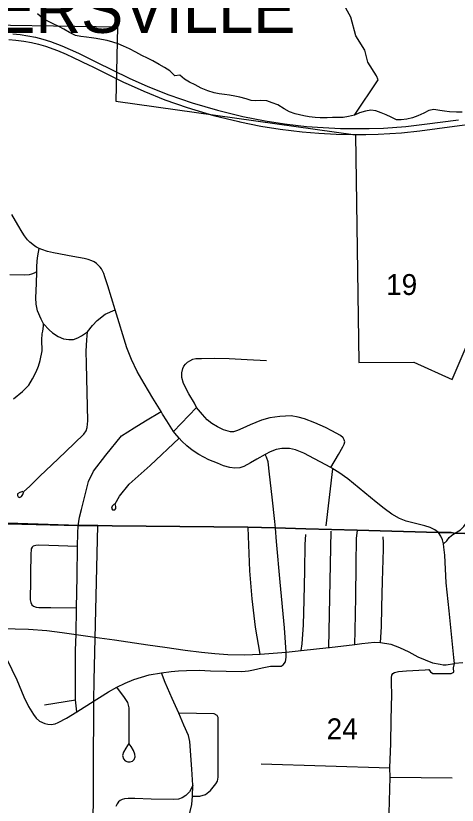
# Model space of a CAD drawing. Extents: x 0 to 34, y 0 to 22.
# Drawn here: x 6.345 to 7.23, y 15.187 to 16.768 of the extents above; entities that cross this region are included whole.
import ezdxf

# ---------------------------------------------------------------- set-up
doc = ezdxf.new("R2010")
doc.units = 0
for name, color, linetype in [('GM_X_City_Street', 7, 'Continuous'), ('GM_X_Corporation', 7, 'Continuous'), ('GM_X_Corporation_Text', 7, 'Continuous'), ('GM_X_County_Road', 7, 'Continuous'), ('GM_X_Minor_River', 7, 'Continuous'), ('GM_X_Section_Text', 7, 'Continuous'), ('GM_X_State_Route', 7, 'Continuous'), ('GM_X_Township_Road', 7, 'Continuous'), ('GM_X_US_Route', 7, 'Continuous')]:
    doc.layers.add(name, color=color, linetype=linetype)

msp = doc.modelspace()

# ---------------------------------------------------------------- linework, layer by layer
at = {"layer": 'GM_X_City_Street'}
for p, q in [((6.6615, 15.9355), (6.7076, 15.9837)), ((6.9669, 15.7469), (6.9804, 15.8611)), ((6.9725, 15.5033), (6.9773, 15.736)), ((6.8369, 15.2705), (7.0949, 15.2625)), ((7.0951, 15.2437), (7.2198, 15.2421))]:
    msp.add_line(p, q, dxfattribs=at)
for points in [[(6.3412, 16.0009), (6.359, 16.0156), (6.3716, 16.0286), (6.379, 16.041), (6.3865, 16.0549), (6.3909, 16.0667), (6.3942, 16.0776), (6.3981, 16.097), (6.3977, 16.1195), (6.3982, 16.1312), (6.3996, 16.1368), (6.4008, 16.1467), (6.4009, 16.1516), (6.3963, 16.1606), (6.389, 16.1776), (6.3862, 16.1905), (6.3855, 16.2032), (6.3867, 16.2322), (6.3875, 16.2555), (6.3879, 16.2647), (6.3886, 16.2776), (6.3894, 16.2877), (6.3924, 16.3018)], [(6.3867, 16.2554), (6.3826, 16.253), (6.3769, 16.2508), (6.3723, 16.2496), (6.3629, 16.2484), (6.3334, 16.2491)], [(6.3594, 15.8154), (6.3537, 15.8133), (6.3492, 15.8108), (6.3487, 15.8074), (6.3504, 15.8046), (6.3532, 15.8035), (6.357, 15.8056), (6.3593, 15.8095), (6.3614, 15.8154), (6.3731, 15.8257), (6.3936, 15.8461), (6.4176, 15.8691), (6.4448, 15.8951), (6.4821, 15.9306), (6.4863, 15.9369), (6.4887, 15.9436), (6.4899, 15.9573), (6.4872, 16.0709), (6.4867, 16.0967), (6.4875, 16.1195), (6.4891, 16.135), (6.4994, 16.1481), (6.5085, 16.1578), (6.5245, 16.1709), (6.5442, 16.1793)], [(6.4009, 16.1516), (6.4125, 16.1393), (6.4188, 16.1334), (6.4301, 16.1261), (6.4412, 16.1214), (6.4515, 16.1196), (6.4612, 16.1202), (6.4697, 16.123), (6.4774, 16.1271), (6.4891, 16.135)], [(6.9767, 15.8634), (6.9916, 15.8896), (7.0005, 15.9049), (7.0032, 15.9106), (7.0043, 15.9151), (7.0035, 15.9189), (7.001, 15.923), (6.9959, 15.9276), (6.9873, 15.9325), (6.9788, 15.9367), (6.9656, 15.9439), (6.9441, 15.953), (6.9234, 15.9611), (6.9109, 15.9647), (6.8969, 15.967), (6.8743, 15.9658), (6.8541, 15.963), (6.8373, 15.9587), (6.8148, 15.9492), (6.7999, 15.9426), (6.7895, 15.9376), (6.7816, 15.9351), (6.7755, 15.9349), (6.7616, 15.9388), (6.7492, 15.9448), (6.7381, 15.9517), (6.7291, 15.9589), (6.7194, 15.9698), (6.7076, 15.9837), (6.7034, 15.9926), (6.6923, 16.0108), (6.6817, 16.0315), (6.6783, 16.0438), (6.6782, 16.0531), (6.6799, 16.0615), (6.6819, 16.0662), (6.6852, 16.0704), (6.6895, 16.0742), (6.6941, 16.0774), (6.7004, 16.0804), (6.706, 16.0817), (6.7177, 16.0821), (6.7436, 16.0826), (6.773, 16.0816), (6.8091, 16.08), (6.8479, 16.0781)], [(6.4704, 15.7468), (6.4733, 15.7644), (6.477, 15.7798), (6.4842, 15.809), (6.4909, 15.8358), (6.5009, 15.8561), (6.5258, 15.8885), (6.5572, 15.927), (6.5824, 15.9433), (6.6054, 15.9573), (6.6364, 15.9757)], [(6.5433, 15.7905), (6.5413, 15.789), (6.5382, 15.7863), (6.5371, 15.7823), (6.539, 15.7786), (6.5438, 15.7786), (6.5459, 15.7815), (6.546, 15.7853), (6.5449, 15.7881), (6.5446, 15.7911), (6.553, 15.8065), (6.5725, 15.8301), (6.6144, 15.8677), (6.6727, 15.9221)], [(6.8868, 15.4941), (6.8838, 15.5423), (6.8748, 15.6341), (6.8679, 15.7153), (6.8655, 15.7422), (6.8643, 15.7556), (6.8589, 15.8043), (6.8538, 15.8505), (6.851, 15.8749), (6.8479, 15.8846), (6.8448, 15.8899)], [(6.8348, 15.4895), (6.8257, 15.544), (6.8192, 15.6004), (6.8142, 15.6565), (6.8107, 15.7437)], [(6.9173, 15.4972), (6.9189, 15.5107), (6.9217, 15.5484), (6.9231, 15.5979), (6.9243, 15.6575), (6.925, 15.7093), (6.9265, 15.7293)], [(7.0243, 15.5092), (7.025, 15.5369), (7.0263, 15.6037), (7.0275, 15.6687), (7.0282, 15.722), (7.0296, 15.7377), (7.0298, 15.739)], [(7.0761, 15.5133), (7.0781, 15.5442), (7.0789, 15.5839), (7.0802, 15.6357), (7.0818, 15.6998), (7.0822, 15.7131), (7.0811, 15.7246)], [(7.0936, 15.1715), (7.0951, 15.2437), (7.0949, 15.2625), (7.0969, 15.311), (7.0975, 15.3585), (7.0985, 15.4099), (7.0978, 15.4311), (7.0979, 15.439), (7.0981, 15.4434), (7.0987, 15.4476), (7.1006, 15.4509), (7.1039, 15.4533), (7.1121, 15.455), (7.1283, 15.4562), (7.1654, 15.4581), (7.1726, 15.4591), (7.1764, 15.4545), (7.1807, 15.4514), (7.2175, 15.4513), (7.2226, 15.4535), (7.2224, 15.4627), (7.2243, 15.4708)], [(6.7001, 15.2275), (6.6978, 15.2596), (6.6943, 15.3147), (6.6911, 15.3269), (6.6822, 15.3475), (6.672, 15.3718), (6.6587, 15.4013), (6.6449, 15.4332), (6.6374, 15.4526)], [(6.5721, 15.3107), (6.5692, 15.3072), (6.5658, 15.3013), (6.5611, 15.2934), (6.5593, 15.2869), (6.561, 15.2802), (6.5647, 15.2761), (6.5701, 15.274), (6.5743, 15.2741), (6.579, 15.2755), (6.5828, 15.2789), (6.5849, 15.2844), (6.584, 15.2898), (6.5813, 15.2968), (6.5767, 15.3048), (6.5728, 15.3105), (6.5724, 15.3273), (6.5728, 15.3624), (6.5727, 15.3826), (6.5699, 15.3928), (6.5635, 15.403), (6.5482, 15.4237)], [(6.6997, 15.2055), (6.7138, 15.2053), (6.7253, 15.2086), (6.7356, 15.2168), (6.746, 15.2302), (6.7493, 15.2354), (6.7506, 15.2436), (6.7508, 15.2882), (6.7511, 15.3627), (6.7486, 15.3673), (6.7429, 15.37), (6.672, 15.3718)], [(6.7001, 15.2275), (6.6967, 15.22), (6.6931, 15.214), (6.686, 15.207), (6.679, 15.2023), (6.6713, 15.1994), (6.6614, 15.1987), (6.6169, 15.1997), (6.5841, 15.2006), (6.5704, 15.2009), (6.5633, 15.2004), (6.5585, 15.1987), (6.5546, 15.1968), (6.5515, 15.194), (6.5485, 15.19), (6.546, 15.1845)], [(6.6911, 15.1605), (6.6979, 15.1888), (6.6997, 15.2055), (6.7001, 15.2275)]]:
    msp.add_lwpolyline(points, dxfattribs=at)
at = {"layer": 'GM_X_Corporation'}
for points in [[(5.8633, 16.7565), (6.5495, 16.7462), (6.5461, 16.597), (7.0261, 16.5297), (7.0326, 16.0736), (7.143, 16.0746), (7.2194, 16.0401), (7.3126, 16.2562)], [(5.4664, 15.7674), (5.6014, 15.7658), (5.6068, 15.7657), (5.6123, 15.7657), (5.7944, 15.7634), (6.4702, 15.7474), (6.8105, 15.7443), (6.8653, 15.7428), (6.9267, 15.7411), (7.0294, 15.7382), (7.1916, 15.7337), (7.2174, 15.7331), (7.2238, 15.7321), (7.3532, 15.7283), (7.8346, 15.7173), (8.2379, 15.708), (8.2436, 15.7079), (8.2556, 15.7096), (8.4088, 15.7047), (8.4164, 15.7046), (8.9, 15.6953), (8.9, 16.3396)], [(4.5503, 14.1), (8.9, 14.1), (8.9, 15.6953), (8.4164, 15.7046), (8.4088, 15.7047), (8.2556, 15.7096), (8.2436, 15.7079), (8.2379, 15.708), (7.8346, 15.7173), (7.3532, 15.7283), (7.2238, 15.7321), (7.2174, 15.7331), (7.1916, 15.7337), (7.0294, 15.7382), (6.9267, 15.7411), (6.8653, 15.7428), (6.8105, 15.7443), (6.4702, 15.7474), (5.7944, 15.7634), (5.6123, 15.7657), (5.6068, 15.7657), (5.6014, 15.7658), (5.4664, 15.7674)], [(6.5, 14.9635), (6.502, 15.3971), (6.5022, 15.4372), (6.5096, 15.7475), (6.4714, 15.7474), (6.2879, 15.7537)]]:
    msp.add_lwpolyline(points, dxfattribs=at)
at = {"layer": 'GM_X_County_Road'}
for points in [[(6.2927, 15.5405), (6.3175, 15.541), (6.371, 15.5398), (6.4077, 15.5372), (6.4382, 15.5331), (6.4667, 15.529)], [(6.2927, 15.5405), (6.2978, 15.5242), (6.3003, 15.5205), (6.3061, 15.514), (6.3122, 15.5073), (6.3174, 15.5004), (6.3474, 15.4383), (6.3618, 15.4045), (6.3711, 15.3851), (6.3807, 15.3689), (6.3866, 15.3614), (6.3929, 15.3557), (6.4036, 15.3508), (6.4096, 15.3495), (6.4166, 15.3492), (6.4241, 15.35), (6.4307, 15.3528), (6.4469, 15.3618), (6.4675, 15.3746), (6.5022, 15.3966), (6.5132, 15.4033)], [(6.4667, 15.529), (6.5131, 15.5224), (6.5429, 15.5182)], [(6.5429, 15.5182), (6.6101, 15.5088), (6.6438, 15.5038), (6.6846, 15.4977), (6.7174, 15.4937), (6.744, 15.4909), (6.7705, 15.4892), (6.8041, 15.4887), (6.8348, 15.4895), (6.8868, 15.4941), (6.9173, 15.4972), (6.9725, 15.5033), (6.9735, 15.5034)], [(6.9735, 15.5034), (7.0243, 15.5092), (7.0384, 15.5113), (7.0642, 15.5137), (7.0761, 15.5133), (7.0966, 15.5096), (7.1137, 15.5034), (7.1326, 15.4946), (7.151, 15.4846), (7.1801, 15.4726), (7.1953, 15.4695), (7.2016, 15.4687), (7.2074, 15.4686), (7.2243, 15.4708)], [(6.8594, 15.4658), (6.8705, 15.466), (6.8769, 15.4658), (6.8809, 15.4687), (6.8856, 15.4747), (6.887, 15.4837), (6.8868, 15.4941)], [(6.5132, 15.4033), (6.531, 15.4142), (6.5482, 15.4237), (6.5644, 15.4318), (6.5822, 15.439), (6.6127, 15.4485), (6.6374, 15.4526), (6.6569, 15.4553), (6.6712, 15.4566), (6.6876, 15.4573), (6.713, 15.4575), (6.7354, 15.4566), (6.7983, 15.4554), (6.8116, 15.4565), (6.8215, 15.4584), (6.8387, 15.4625), (6.8554, 15.4658), (6.8594, 15.4658)]]:
    msp.add_lwpolyline(points, dxfattribs=at)
at = {"layer": 'GM_X_Minor_River'}
for points in [[(7.0236, 16.5692), (7.0711, 16.6397), (7.0676, 16.6477), (7.0504, 16.6751), (7.0443, 16.6993), (7.0264, 16.7279), (7.0163, 16.7654), (6.9905, 16.8128)], [(7.0236, 16.5692), (7.0119, 16.5662), (7.0009, 16.5647), (6.9903, 16.5647), (6.9796, 16.5644), (6.969, 16.5637), (6.955, 16.5636), (6.945, 16.5645), (6.9328, 16.566), (6.9221, 16.5679), (6.9053, 16.5719), (6.8937, 16.5758), (6.8829, 16.5819), (6.8705, 16.5899), (6.8593, 16.5941), (6.8482, 16.5975), (6.836, 16.5983), (6.8265, 16.598), (6.8166, 16.5984), (6.8066, 16.6019), (6.794, 16.6053), (6.784, 16.6073), (6.7733, 16.6092), (6.7638, 16.6108), (6.7527, 16.6116), (6.7427, 16.614), (6.7301, 16.6178), (6.7166, 16.6234), (6.705, 16.6299), (6.6934, 16.6352), (6.6837, 16.6414), (6.674, 16.6495), (6.6641, 16.648), (6.6543, 16.6576), (6.6431, 16.6648), (6.6326, 16.6706), (6.6202, 16.6778), (6.609, 16.6832), (6.5982, 16.6889), (6.5862, 16.6954), (6.5731, 16.7018), (6.5615, 16.7075), (6.5507, 16.7121), (6.5396, 16.7156), (6.5284, 16.7186), (6.517, 16.7206), (6.5067, 16.7225), (6.4971, 16.7237), (6.4868, 16.7253), (6.4757, 16.7269), (6.4654, 16.7288), (6.4531, 16.7345), (6.4414, 16.741), (6.4314, 16.7464), (6.4206, 16.7521), (6.4098, 16.7571), (6.3993, 16.7636), (6.3891, 16.7721)], [(7.2397, 16.5752), (7.2283, 16.5752), (7.2139, 16.5759), (7.2043, 16.5768), (7.1948, 16.5787), (7.1825, 16.5806), (7.1727, 16.5784), (7.1626, 16.5732), (7.1506, 16.5675), (7.1397, 16.5637), (7.1288, 16.5611), (7.1174, 16.5596), (7.1079, 16.5601), (7.0971, 16.565), (7.0874, 16.5697), (7.0771, 16.5735), (7.0667, 16.5778), (7.0567, 16.579), (7.0458, 16.5771), (7.0341, 16.5737), (7.0236, 16.5692)]]:
    msp.add_lwpolyline(points, dxfattribs=at)
at = {"layer": 'GM_X_State_Route'}
for points in [[(7.2243, 15.4708), (7.223, 15.4834), (7.2132, 15.5765), (7.2075, 15.6327), (7.2045, 15.688), (7.2031, 15.7039), (7.2021, 15.711), (7.1998, 15.719), (7.1969, 15.726), (7.1918, 15.7331), (7.1845, 15.7391), (7.1757, 15.7435), (7.1647, 15.7468), (7.1516, 15.7499), (7.1276, 15.7563), (7.1139, 15.7616), (7.0988, 15.77), (7.0831, 15.7813), (7.0673, 15.7942), (7.0103, 15.841), (6.9928, 15.8535), (6.9804, 15.8611), (6.9767, 15.8634), (6.9221, 15.8923), (6.9057, 15.8988), (6.8935, 15.9016), (6.8785, 15.9016), (6.8672, 15.8995), (6.8549, 15.8951), (6.8448, 15.8899), (6.8282, 15.8802), (6.8156, 15.8726), (6.8025, 15.8657), (6.7941, 15.8628), (6.7841, 15.862), (6.7744, 15.8633), (6.7614, 15.8672), (6.7494, 15.8721), (6.7324, 15.8792), (6.7124, 15.8893), (6.6985, 15.8983), (6.6879, 15.9068), (6.6781, 15.916), (6.6727, 15.9221), (6.6642, 15.9323), (6.6615, 15.9355), (6.6478, 15.9568), (6.6395, 15.9705), (6.6364, 15.9757), (6.6199, 16.0026), (6.6024, 16.0315), (6.5887, 16.0558), (6.577, 16.0796), (6.5676, 16.1034), (6.5442, 16.1793), (6.5299, 16.2271), (6.5241, 16.2454), (6.5217, 16.252), (6.5193, 16.2573), (6.5172, 16.2612), (6.5145, 16.2647), (6.5105, 16.269), (6.5069, 16.2722), (6.5026, 16.2752), (6.4978, 16.2776), (6.4904, 16.2802), (6.4824, 16.2822), (6.4599, 16.2864), (6.4208, 16.2936), (6.4092, 16.2962), (6.3975, 16.2998), (6.3924, 16.3018), (6.3873, 16.3046), (6.3834, 16.307), (6.3793, 16.31), (6.3737, 16.3149), (6.369, 16.3198), (6.3632, 16.3274), (6.3586, 16.3345), (6.3496, 16.3492), (6.3375, 16.3704)], [(7.2407, 15.4724), (7.2243, 15.4708)]]:
    msp.add_lwpolyline(points, dxfattribs=at)
at = {"layer": 'GM_X_Township_Road'}
msp.add_line((6.4029, 15.3885), (6.4651, 15.3981), dxfattribs=at)
for points in [[(7.2021, 15.711), (7.2088, 15.7167), (7.2135, 15.7234), (7.2179, 15.7276), (7.2227, 15.7308), (7.224, 15.7315), (7.2359, 15.7387), (7.243, 15.7453), (7.2521, 15.7581), (7.2684, 15.7841), (7.2837, 15.8083), (7.3057, 15.8429), (7.3177, 15.8615), (7.3225, 15.8657), (7.3304, 15.8691), (7.3921, 15.8918), (7.4243, 15.9051), (7.4517, 15.9179), (7.4806, 15.9299), (7.4949, 15.9367), (7.4965, 15.9378)], [(6.4675, 15.3746), (6.4651, 15.3981), (6.4649, 15.498), (6.4667, 15.529), (6.4672, 15.5824), (6.4686, 15.6454), (6.4689, 15.7056), (6.4699, 15.7319), (6.4704, 15.7468)], [(6.4689, 15.7056), (6.4116, 15.7074), (6.391, 15.7079), (6.3854, 15.7076), (6.3804, 15.7063), (6.3782, 15.7039), (6.3765, 15.7009), (6.3755, 15.6888), (6.3749, 15.652), (6.3749, 15.6295), (6.3743, 15.6072), (6.3744, 15.5984), (6.3755, 15.593), (6.3778, 15.5887), (6.3813, 15.5856), (6.3863, 15.5837), (6.3914, 15.5833), (6.4155, 15.583), (6.4672, 15.5824)]]:
    msp.add_lwpolyline(points, dxfattribs=at)
at = {"layer": 'GM_X_US_Route'}
for points in [[(6.3395, 16.732), (6.3544, 16.7305), (6.3698, 16.7282), (6.385, 16.725), (6.3995, 16.7216), (6.4148, 16.7168), (6.4378, 16.708), (6.4546, 16.7007), (6.4708, 16.6933), (6.506, 16.6758), (6.5724, 16.6431), (6.6102, 16.6263), (6.6523, 16.6097), (6.6986, 16.5937), (6.7498, 16.5788), (6.8003, 16.5665), (6.8448, 16.5577), (6.8834, 16.5518), (6.9275, 16.5467), (6.961, 16.5441), (6.9955, 16.5426), (7.0289, 16.5423), (7.0531, 16.5424), (7.0822, 16.5434), (7.1265, 16.5467), (7.164, 16.5508), (7.2322, 16.56)], [(6.3313, 16.7205), (6.3459, 16.7194), (6.3619, 16.7172), (6.3767, 16.7146), (6.3913, 16.7112), (6.4053, 16.7073), (6.4293, 16.6988), (6.4467, 16.6913), (6.4607, 16.6849), (6.4922, 16.6694)], [(6.4922, 16.6694), (6.4985, 16.6663), (6.5628, 16.6346), (6.5647, 16.6338)], [(6.5647, 16.6338), (6.6017, 16.6171), (6.6437, 16.6001), (6.6887, 16.5843), (6.7416, 16.5686), (6.7919, 16.5562), (6.7939, 16.5558)], [(6.7939, 16.5558), (6.8365, 16.5471), (6.8753, 16.5409), (6.9192, 16.5356), (6.9526, 16.5328), (6.9874, 16.5309), (7.0208, 16.5302), (7.0447, 16.5303)], [(7.0447, 16.5303), (7.0468, 16.5303), (7.0714, 16.5312), (7.1177, 16.5338), (7.1549, 16.5376), (7.2242, 16.5468), (7.265, 16.5525)]]:
    msp.add_lwpolyline(points, dxfattribs=at)

# ---------------------------------------------------------------- texts
at = {"layer": 'GM_X_Corporation_Text'}
msp.add_text('WINTERSVILLE', height=0.094697, rotation=0, dxfattribs=at).set_placement((5.9768, 16.7339))
at = {"layer": 'GM_X_Section_Text'}
for s, p in [('19', (7.0872, 16.209)), ('24', (6.9681, 15.3193))]:
    msp.add_text(s, height=0.04186, rotation=0, dxfattribs=at).set_placement(p)

doc.saveas('drawing.dxf')
